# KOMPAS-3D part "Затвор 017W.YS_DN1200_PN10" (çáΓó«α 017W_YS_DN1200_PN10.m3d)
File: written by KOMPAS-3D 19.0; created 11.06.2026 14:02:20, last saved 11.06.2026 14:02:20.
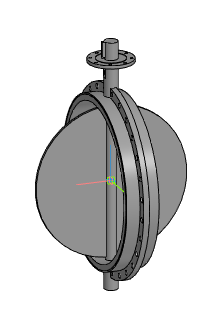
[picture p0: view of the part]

Document properties: Автор: Евгений; Полное имя файла: Z:\3.Личные\kachalov\001_3d для проектировщиков\x.x Тип 017W.Y(S) Затвор дисковый поворотный межфланцевый\_stp_Затвор 017W.YS_DN32-DN1200\Затвор 017W_YS_DN1200_PN10.m3d

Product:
- Part/product: Затвор 017W.YS_DN1200_PN10

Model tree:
1. Операция без истории:1  (labels: Затвор 017W.YS_DN1200_PN10)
